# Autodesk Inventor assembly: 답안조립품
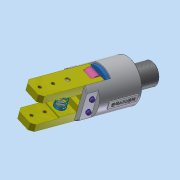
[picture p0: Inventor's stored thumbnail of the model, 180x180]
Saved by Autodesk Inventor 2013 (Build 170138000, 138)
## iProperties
Created: 2019-02
Part Number: 답안조립품
Document SubType Name: Assembly
Designer: Administrator
Author: Administrator
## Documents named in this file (11)
- C:\Users\Administrator\Desktop\490207V1018\답안조립품.iam
- C:\Users\Administrator\Desktop\490207V1018\본체.ipt
- C:\Users\Administrator\Desktop\490207V1018\E-링.ipt
- C:\Users\Administrator\Desktop\490207V1018\O-링.ipt
- C:\Users\Administrator\Desktop\490207V1018\가이드핀.ipt
- C:\Users\Administrator\Desktop\490207V1018\부시.ipt
- C:\Users\Administrator\Desktop\490207V1018\스프링.ipt
- C:\Users\Administrator\Desktop\490207V1018\평행핀 6x28.ipt
- C:\Users\Administrator\Desktop\490207V1018\피스톤.ipt
- C:\Users\Administrator\Desktop\490207V1018\핀.ipt
- C:\Users\Administrator\Desktop\490207V1018\핑거.ipt
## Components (13 placed, 6 different names)
1. E-링:1
2. O-링:1
3. 가이드핀:1
4. 피스톤:1
5. 핀:1
6. 핑거:1
7. O-링:2
8. 핑거:2
9. 핀:2
10. E-링:2
11. E-링:3
12. E-링:4
13. 가이드핀:2
